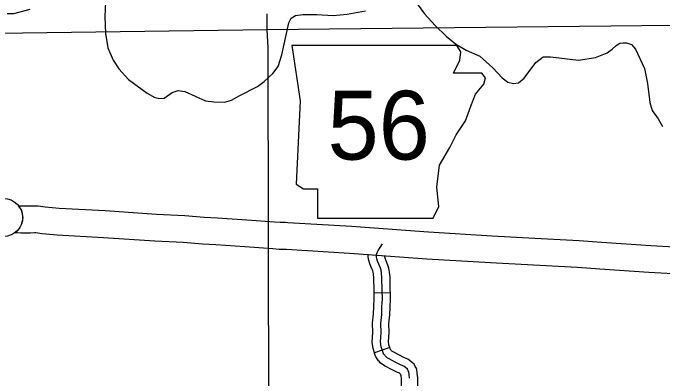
# Model space of a CAD drawing. Extents: x 1377389 to 1380723, y 1168351 to 1170484.
# Drawn here: x 1379167.2 to 1379286.7, y 1169089.4 to 1169156.6 of the extents above; entities that cross this region are included whole.
import ezdxf

# ---------------------------------------------------------------- set-up
doc = ezdxf.new("R2010")
doc.units = 0
doc.layers.add('B_Fill', color=7, linetype='Continuous')

msp = doc.modelspace()

# ---------------------------------------------------------------- linework, layer by layer
at = {"layer": 'B_Fill'}
for p, q in [((1379236.72, 1169105.03), (1379233.72, 1169104.95)), ((1379236.64, 1169094.99), (1379233.81, 1169093.99))]:
    msp.add_line(p, q, dxfattribs=at)
for points in [[(1379184.24, 1169158.63), (1379184.13, 1169155.9), (1379184.24, 1169152.82), (1379184.71, 1169150.14), (1379185.66, 1169147.86), (1379186.7, 1169146.27), (1379188.5, 1169144.35), (1379191.95, 1169141.81), (1379193.35, 1169141.02), (1379194.25, 1169140.8), (1379195.09, 1169140.87), (1379196.51, 1169141.91), (1379197.64, 1169142.29), (1379198.88, 1169142.11), (1379202.68, 1169140.42), (1379204.19, 1169140.19), (1379206.2, 1169140.15), (1379207.49, 1169140.51), (1379209, 1169141.38), (1379212.28, 1169143.04), (1379213.5, 1169143.98), (1379215.05, 1169145.41), (1379216.05, 1169146.72), (1379216.72, 1169148.88), (1379218.01, 1169154.78), (1379218.45, 1169155.6), (1379219.23, 1169156.12), (1379220.6, 1169156.28), (1379223.15, 1169156.28), (1379226.21, 1169156.12), (1379228.77, 1169156.38), (1379232.11, 1169156.94)], [(1379241.66, 1169158.27), (1379243, 1169156.39), (1379244.94, 1169154.29), (1379246.97, 1169152.29), (1379248.71, 1169150.87)], [(1379166.18, 1169156.49), (1379167.39, 1169156.45), (1379170.4, 1169157.28)], [(1379214.06, 1169153.54), (1379214.02, 1169156.41)], [(1379150.84, 1169152.68), (1379214.06, 1169153.54)], [(1379214.06, 1169153.54), (1379306.05, 1169154.5)], [(1379214.37, 1169047.94), (1379214.22, 1169150.15), (1379214.06, 1169153.54)], [(1379248.71, 1169150.87), (1379250.7, 1169149.75), (1379253.19, 1169148.64), (1379255.59, 1169146.46), (1379257.29, 1169144.63), (1379258.35, 1169143.84), (1379259.41, 1169143.59), (1379260.33, 1169143.7), (1379261.36, 1169144.55), (1379263.48, 1169147.48), (1379264.87, 1169148.52), (1379266.22, 1169148.48), (1379271.37, 1169147.88), (1379274.48, 1169148.38), (1379276.67, 1169149.21), (1379277.59, 1169149.89), (1379278.28, 1169150.6), (1379278.99, 1169151), (1379279.59, 1169151.1), (1379280.17, 1169151.05), (1379281.11, 1169150.78), (1379281.88, 1169149.89), (1379283.54, 1169146.38), (1379284.09, 1169143.59), (1379284.48, 1169140.1), (1379284.94, 1169138.59), (1379286.03, 1169137.09), (1379286.81, 1169135.65)], [(1379167.61, 1169116.12), (1379167.95, 1169116.32), (1379168.38, 1169116.8), (1379168.64, 1169117.23), (1379168.87, 1169117.75), (1379169.01, 1169118.37), (1379169.06, 1169118.95), (1379168.97, 1169119.66), (1379168.77, 1169120.3), (1379168.26, 1169121.08)], [(1379168.26, 1169121.08), (1379168.82, 1169121.05), (1379170.3, 1169121.05), (1379171.04, 1169121.09), (1379171.85, 1169121.09), (1379173.13, 1169120.88), (1379174.43, 1169120.77), (1379175.71, 1169120.65), (1379184.19, 1169120.19), (1379193.64, 1169119.53), (1379198.9, 1169119.3), (1379202.45, 1169119), (1379204.88, 1169118.86), (1379210.27, 1169118.47), (1379215.41, 1169118.11), (1379216.43, 1169118.05), (1379217.38, 1169118.03), (1379217.85, 1169118.01), (1379229.56, 1169117.3), (1379243.77, 1169116.26), (1379255.46, 1169115.53), (1379263.32, 1169115.12), (1379271.47, 1169114.67)], [(1379271.16, 1169109.68), (1379263.05, 1169110.12), (1379255.17, 1169110.54), (1379243.44, 1169111.27), (1379229.22, 1169112.31), (1379217.59, 1169113.02), (1379217.23, 1169113.03), (1379216.23, 1169113.05), (1379215.07, 1169113.12), (1379209.92, 1169113.49), (1379204.56, 1169113.87), (1379202.1, 1169114.01), (1379198.58, 1169114.3), (1379193.36, 1169114.54), (1379183.88, 1169115.2), (1379175.36, 1169115.67), (1379174, 1169115.78), (1379172.51, 1169115.91), (1379171.44, 1169116.09), (1379171.17, 1169116.09), (1379170.43, 1169116.05), (1379168.65, 1169116.05), (1379167.61, 1169116.12)], [(1379240.26, 1169089.35), (1379240.18, 1169089.94), (1379240.14, 1169090.48), (1379239.97, 1169090.69), (1379239.85, 1169090.98), (1379239.18, 1169091.53), (1379238.68, 1169091.74), (1379237.59, 1169092.28), (1379236.5, 1169092.87), (1379236.13, 1169093.08), (1379235.92, 1169093.24), (1379235.75, 1169093.45), (1379235.67, 1169093.54), (1379235.54, 1169093.7), (1379235.37, 1169094), (1379235.25, 1169094.41), (1379235, 1169095.12), (1379234.87, 1169096), (1379235, 1169097.76), (1379234.96, 1169099.39), (1379235.12, 1169101.07), (1379235.16, 1169102.49), (1379235.25, 1169103.95), (1379235.21, 1169105.46), (1379235.16, 1169107.88), (1379235.08, 1169108.68), (1379235, 1169109.22), (1379234.87, 1169109.6), (1379234.58, 1169110.35), (1379234.33, 1169110.9), (1379234.2, 1169111.31), (1379234.16, 1169111.69), (1379234.16, 1169112.07), (1379234.29, 1169112.49), (1379234.45, 1169112.86), (1379234.83, 1169113.41), (1379235.29, 1169114.08)], [(1379271.47, 1169114.67), (1379275.61, 1169114.38), (1379284.65, 1169113.77), (1379289.05, 1169113.52)], [(1379233.72, 1169104.95), (1379233.71, 1169105.42), (1379233.67, 1169107.79), (1379233.59, 1169108.49), (1379233.53, 1169108.87), (1379233.46, 1169109.09), (1379233.2, 1169109.77), (1379232.92, 1169110.36), (1379232.73, 1169111.01), (1379232.66, 1169111.61), (1379232.66, 1169112.15)], [(1379236.72, 1169105.03), (1379236.71, 1169105.49), (1379236.66, 1169107.98), (1379236.57, 1169108.87), (1379236.46, 1169109.58), (1379236.28, 1169110.11), (1379235.96, 1169110.94), (1379235.74, 1169111.43), (1379235.68, 1169111.62), (1379235.66, 1169111.77), (1379235.66, 1169111.85), (1379235.67, 1169111.88)], [(1379288.77, 1169108.52), (1379284.34, 1169108.78), (1379275.27, 1169109.39), (1379271.16, 1169109.68)], [(1379233.81, 1169093.99), (1379233.53, 1169094.77), (1379233.36, 1169095.95), (1379233.5, 1169097.79), (1379233.45, 1169099.45), (1379233.62, 1169101.16), (1379233.67, 1169102.55), (1379233.75, 1169103.97), (1379233.72, 1169104.95)], [(1379236.64, 1169094.99), (1379236.46, 1169095.48), (1379236.38, 1169096.06), (1379236.5, 1169097.73), (1379236.46, 1169099.34), (1379236.62, 1169100.97), (1379236.66, 1169102.42), (1379236.75, 1169103.93), (1379236.72, 1169105.03)], [(1379241.78, 1169086.53), (1379241.76, 1169088.81), (1379241.76, 1169089.46), (1379241.67, 1169090.1), (1379241.6, 1169091.06), (1379241.27, 1169091.47), (1379241.08, 1169091.91), (1379239.95, 1169092.83), (1379239.3, 1169093.1), (1379238.28, 1169093.61), (1379237.22, 1169094.18), (1379236.98, 1169094.32), (1379236.87, 1169094.45), (1379236.8, 1169094.52), (1379236.8, 1169094.53), (1379236.76, 1169094.59), (1379236.67, 1169094.88), (1379236.64, 1169094.99)], [(1379238.78, 1169086.51), (1379238.76, 1169088.8), (1379238.76, 1169089.25), (1379238.69, 1169089.77), (1379238.68, 1169089.91), (1379238.67, 1169089.91), (1379238.61, 1169090.05), (1379238.4, 1169090.23), (1379238.05, 1169090.37), (1379236.9, 1169090.95), (1379235.78, 1169091.55), (1379235.29, 1169091.83), (1379234.85, 1169092.18), (1379234.63, 1169092.45), (1379234.53, 1169092.55), (1379234.28, 1169092.88), (1379233.99, 1169093.4), (1379233.82, 1169093.95), (1379233.81, 1169093.99)]]:
    msp.add_lwpolyline(points, dxfattribs=at)
msp.add_lwpolyline([(1379218.56, 1169150.57), (1379220.08, 1169140.42), (1379219.4, 1169125.03), (1379220.75, 1169124.18), (1379223.29, 1169124.18), (1379223.29, 1169118.77), (1379244.61, 1169118.77), (1379245.62, 1169120.97), (1379245.29, 1169124.52), (1379245.79, 1169128.58), (1379247.65, 1169131.8), (1379248.84, 1169134.16), (1379250.53, 1169136.7), (1379251.55, 1169139.41), (1379252.39, 1169141.61), (1379253.91, 1169143.47), (1379254.25, 1169144.65), (1379253.58, 1169145.5), (1379248.33, 1169145.5), (1379249.51, 1169147.87), (1379249.68, 1169149.39), (1379248.98, 1169150.56)], close=True, dxfattribs=at)
msp.add_circle((1379165.51, 1169118.92), 3.5, dxfattribs=at)

# ---------------------------------------------------------------- texts
msp.add_text('56', height=12.672, dxfattribs=at).set_placement((1379225.15, 1169129.58))

doc.saveas('drawing.dxf')
